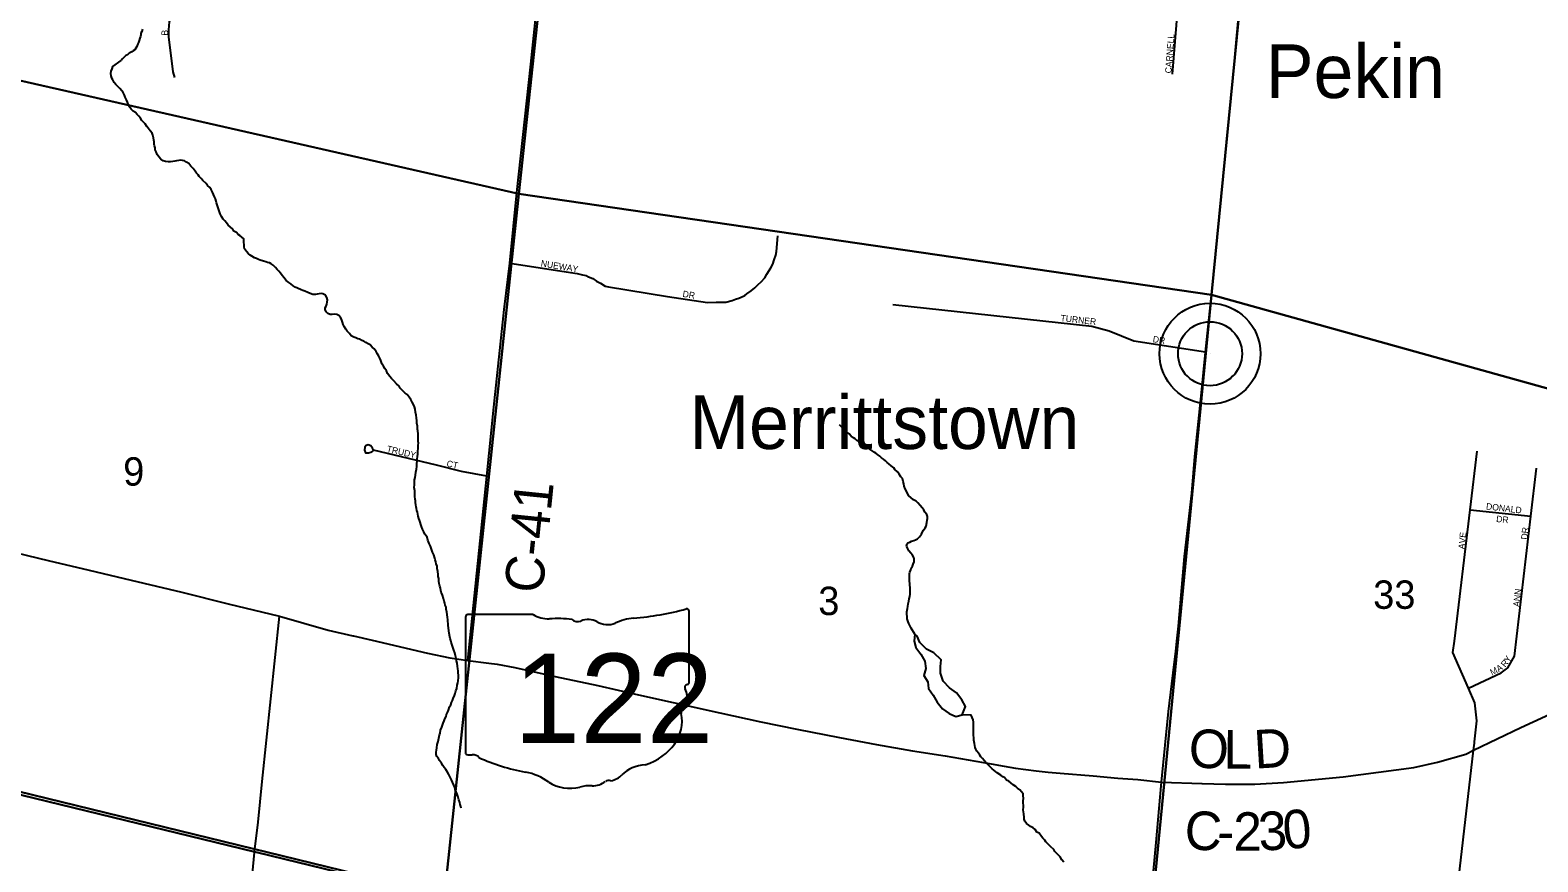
# Model space of a CAD drawing. Extents: x 0 to 1064, y 0 to 440.
# Drawn here: x 222.52 to 258.1, y 292.66 to 312.28 of the extents above; entities that cross this region are included whole.
import ezdxf

# ---------------------------------------------------------------- set-up
doc = ezdxf.new("R2010")
doc.units = 0
for name, color, linetype in [('GM_X_County_Road', 7, 'Continuous'), ('GM_X_County_Road_Text', 7, 'Continuous'), ('GM_X_Minor_Lake', 7, 'Continuous'), ('GM_X_Minor_River', 7, 'Continuous'), ('GM_X_Section', 7, 'Continuous'), ('GM_X_Section_Text', 7, 'Continuous'), ('GM_X_State_Location', 7, 'Continuous'), ('GM_X_State_Route', 7, 'Continuous'), ('GM_X_State_Shield', 7, 'Continuous'), ('GM_X_Township', 7, 'Continuous'), ('GM_X_Township_Subdivision', 7, 'Continuous'), ('GM_X_Township_Subdivision_Text', 7, 'Continuous'), ('GM_X_Unincorporated', 7, 'Continuous'), ('GM_X_Unincorporated_Location', 7, 'Continuous'), ('GM_X_Unincorporated_Text', 7, 'Continuous')]:
    doc.layers.add(name, color=color, linetype=linetype)

msp = doc.modelspace()

# ---------------------------------------------------------------- linework, layer by layer
at = {"layer": 'GM_X_County_Road'}
for points in [[(232.845, 297.415), (233.296, 301.759), (233.463, 303.386), (233.702, 305.691), (233.837, 306.783), (234.001, 308.45), (234.335, 311.479), (234.642, 314.418), (234.9, 316.803)], [(250.165, 294.513), (250.171, 294.513), (250.722, 294.492), (251.418, 294.496), (252.094, 294.534), (253.503, 294.667), (255.166, 294.889), (255.73, 295.017), (256.392, 295.206), (256.58, 295.296), (257.697, 295.829), (258.859, 296.365), (259.226, 296.54), (259.61, 296.696), (259.922, 296.816), (260.414, 296.936), (260.779, 297.03), (261.418, 297.217), (262.042, 297.399), (262.551, 297.565), (263.103, 297.778), (266.941, 299.839), (267.217, 299.997)], [(227.812, 292.884), (227.814, 292.901), (227.897, 293.599), (227.997, 294.56), (228.401, 298.462)], [(249.215, 294.545), (250.165, 294.513)], [(227.217, 256.331), (227.021, 256.544), (226.463, 257.231), (226.198, 257.65), (225.438, 259.12), (225.221, 259.508), (225.122, 259.711), (225.097, 259.973), (225.685, 266.061), (225.937, 268.726), (226.312, 273.171), (227.313, 284.338), (227.421, 286.562), (227.469, 287.662), (227.522, 288.708), (227.683, 291.298), (227.726, 291.973), (227.812, 292.884)]]:
    msp.add_lwpolyline(points, dxfattribs=at)
at = {"layer": 'GM_X_Minor_Lake'}
for points in [[(243.392, 298.033), (243.376, 297.87), (243.421, 297.716), (243.539, 297.562), (243.632, 297.395), (243.653, 297.224), (243.606, 297.061), (243.7, 296.907), (243.72, 296.754), (243.826, 296.594), (243.919, 296.433), (244.049, 296.272), (244.205, 296.165), (244.362, 296.094), (244.515, 296.133)], [(244.515, 296.133), (244.587, 296.326), (244.505, 296.486), (244.375, 296.647), (244.214, 296.767), (244.065, 296.922), (244.003, 297.113), (244.001, 297.271), (244.017, 297.428), (243.844, 297.591), (243.67, 297.68), (243.515, 297.836), (243.452, 297.989), (243.392, 298.033)]]:
    msp.add_lwpolyline(points, dxfattribs=at)
at = {"layer": 'GM_X_Minor_River'}
for points in [[(225.168, 312.302), (225.154, 312.247), (225.135, 312.211), (225.134, 312.175), (225.121, 312.133), (225.107, 312.09), (225.094, 312.036), (225.075, 311.994), (225.061, 311.958), (225.036, 311.898), (225.016, 311.856), (224.991, 311.82), (224.954, 311.796), (224.917, 311.773), (224.855, 311.738), (224.818, 311.702), (224.781, 311.685), (224.744, 311.65), (224.7, 311.608), (224.668, 311.566)], [(226.442, 308.909), (226.413, 308.958), (226.366, 309.02), (226.313, 309.077), (226.267, 309.133), (226.213, 309.171), (226.165, 309.197), (226.117, 309.21), (226.074, 309.212), (226.032, 309.207), (225.976, 309.196), (225.934, 309.192), (225.885, 309.181), (225.83, 309.177), (225.775, 309.178), (225.714, 309.18), (225.66, 309.2), (225.606, 309.238), (225.553, 309.294), (225.519, 309.35), (225.49, 309.412), (225.474, 309.461), (225.469, 309.51), (225.458, 309.552), (225.448, 309.595), (225.443, 309.644), (225.438, 309.687), (225.434, 309.741), (225.418, 309.802), (225.401, 309.852), (225.354, 309.908), (225.302, 309.97), (225.273, 310.013), (225.232, 310.069), (225.197, 310.113), (225.155, 310.151), (225.121, 310.206), (225.086, 310.25), (225.044, 310.294), (225.003, 310.337), (224.95, 310.375), (224.903, 310.419), (224.862, 310.475), (224.839, 310.518), (224.816, 310.58), (224.794, 310.641), (224.766, 310.703), (224.749, 310.752), (224.714, 310.808), (224.685, 310.851), (224.639, 310.907), (224.597, 310.945), (224.544, 311.001), (224.503, 311.051), (224.469, 311.107), (224.446, 311.15), (224.429, 311.205), (224.425, 311.26), (224.433, 311.314), (224.453, 311.368), (224.473, 311.422), (224.668, 311.566)], [(230.204, 305.023), (230.156, 305.043), (230.096, 305.075), (230.055, 305.125), (230.002, 305.181), (229.968, 305.231), (229.927, 305.293), (229.904, 305.342), (229.888, 305.391), (229.877, 305.44), (229.848, 305.495), (229.802, 305.551), (229.754, 305.577), (229.699, 305.579), (229.644, 305.574), (229.601, 305.576), (229.547, 305.596), (229.506, 305.639), (229.483, 305.689), (229.485, 305.731), (229.504, 305.773), (229.524, 305.815), (229.532, 305.869), (229.534, 305.918), (229.523, 305.973), (229.488, 306.028), (229.429, 306.061), (229.386, 306.068), (229.343, 306.063), (229.294, 306.053), (229.252, 306.048), (229.191, 306.05), (229.131, 306.07), (229.07, 306.09), (228.998, 306.123), (228.956, 306.142), (228.914, 306.155), (228.83, 306.194), (228.77, 306.221), (228.723, 306.252), (228.669, 306.297), (228.628, 306.328), (228.562, 306.379), (228.51, 306.447), (228.469, 306.491), (228.428, 306.547), (228.387, 306.597), (228.346, 306.64), (228.311, 306.684), (228.258, 306.74), (228.21, 306.766), (228.168, 306.792), (228.12, 306.805), (228.078, 306.819), (228.023, 306.833), (227.951, 306.859), (227.909, 306.872), (227.861, 306.892), (227.813, 306.912), (227.753, 306.95), (227.711, 306.976), (227.67, 307.007), (227.623, 307.057), (227.576, 307.126), (227.572, 307.168), (227.568, 307.229), (227.563, 307.272), (227.564, 307.32), (227.56, 307.363), (227.518, 307.401), (227.471, 307.438), (227.429, 307.458), (227.388, 307.508), (227.328, 307.54), (227.299, 307.589), (227.24, 307.64), (227.193, 307.684), (227.152, 307.74), (227.111, 307.783), (227.076, 307.827), (227.035, 307.889), (227.001, 307.951), (226.979, 308.018), (226.968, 308.067), (226.951, 308.116), (226.935, 308.165), (226.918, 308.208), (226.907, 308.251), (226.891, 308.3), (226.868, 308.349), (226.845, 308.405), (226.823, 308.46), (226.794, 308.522), (226.759, 308.571), (226.706, 308.621), (226.677, 308.665), (226.594, 308.734), (226.559, 308.784), (226.512, 308.828), (226.483, 308.871), (226.442, 308.909)], [(232.121, 299.64), (232.104, 299.689), (232.094, 299.738), (232.077, 299.787), (232.066, 299.83), (232.044, 299.903), (232.016, 299.971), (231.988, 300.039), (231.966, 300.112), (231.938, 300.174), (231.904, 300.254), (231.888, 300.321), (231.835, 300.389), (231.807, 300.451), (231.778, 300.512), (231.756, 300.574), (231.739, 300.617), (231.723, 300.678), (231.706, 300.721), (231.695, 300.764), (231.679, 300.819), (231.668, 300.862), (231.658, 300.911), (231.647, 300.954), (231.636, 300.996), (231.631, 301.039), (231.621, 301.088), (231.616, 301.137), (231.612, 301.179), (231.607, 301.222), (231.597, 301.283), (231.599, 301.35), (231.595, 301.417), (231.585, 301.49), (231.588, 301.556), (231.59, 301.629), (231.591, 301.672), (231.606, 301.732), (231.613, 301.786), (231.622, 301.853), (231.636, 301.925), (231.645, 301.992), (231.647, 302.052), (231.649, 302.119), (231.65, 302.162), (231.658, 302.222), (231.666, 302.282), (231.669, 302.349), (231.677, 302.416), (231.679, 302.495), (231.681, 302.537), (231.676, 302.58), (231.678, 302.622), (231.679, 302.665), (231.674, 302.707), (231.676, 302.756), (231.666, 302.829), (231.661, 302.872), (231.658, 302.938), (231.648, 303.012), (231.643, 303.066), (231.634, 303.139), (231.63, 303.2), (231.614, 303.268), (231.604, 303.341), (231.587, 303.396), (231.565, 303.451), (231.536, 303.507), (231.502, 303.568), (231.467, 303.624), (231.42, 303.686), (231.373, 303.718), (231.331, 303.756), (231.29, 303.794), (231.249, 303.837), (231.226, 303.881), (231.167, 303.937), (231.102, 304.006), (231.049, 304.068), (231.008, 304.112), (230.956, 304.186), (230.927, 304.242), (230.893, 304.304), (230.858, 304.353), (230.829, 304.403), (230.812, 304.446), (230.795, 304.489), (230.773, 304.544), (230.744, 304.594), (230.71, 304.655), (230.681, 304.699), (230.634, 304.761), (230.593, 304.805), (230.54, 304.861), (230.498, 304.88), (230.444, 304.912), (230.39, 304.944), (230.348, 304.964), (230.294, 304.99), (230.252, 305.003), (230.204, 305.023)], [(241.791, 302.802), (241.749, 302.833), (241.708, 302.877), (241.661, 302.921), (241.62, 302.971)], [(243.392, 298.033), (243.307, 298.178), (243.284, 298.221), (243.255, 298.283), (243.238, 298.326), (243.216, 298.399), (243.212, 298.454), (243.208, 298.509), (243.21, 298.557), (243.217, 298.599), (243.224, 298.642), (243.232, 298.684), (243.24, 298.75), (243.254, 298.811), (243.262, 298.865), (243.276, 298.919), (243.284, 298.974), (243.286, 299.022), (243.288, 299.083), (243.283, 299.132), (243.279, 299.186), (243.274, 299.229), (243.27, 299.284), (243.266, 299.339), (243.267, 299.387), (243.27, 299.454), (243.277, 299.496), (243.297, 299.55), (243.311, 299.592), (243.336, 299.634), (243.356, 299.688), (243.377, 299.742), (243.379, 299.802), (243.374, 299.845), (243.339, 299.895), (243.304, 299.944), (243.257, 300), (243.228, 300.044), (243.206, 300.099), (243.201, 300.142), (243.227, 300.19), (243.276, 300.206), (243.32, 300.229), (243.369, 300.24), (243.412, 300.257), (243.455, 300.28), (243.505, 300.327), (243.55, 300.392), (243.57, 300.434), (243.596, 300.488), (243.64, 300.541), (243.66, 300.583), (243.675, 300.668), (243.689, 300.722), (243.69, 300.764), (243.692, 300.813), (243.675, 300.856), (243.628, 300.912), (243.606, 300.967), (243.565, 301.017), (243.524, 301.067), (243.465, 301.129), (243.424, 301.173), (243.364, 301.205), (243.299, 301.256), (243.257, 301.294), (243.223, 301.349), (243.2, 301.405), (243.165, 301.46), (243.143, 301.528), (243.133, 301.583), (243.123, 301.638), (243.1, 301.705), (243.065, 301.749), (243.025, 301.811), (242.984, 301.86), (242.925, 301.917), (242.896, 301.96), (242.836, 302.005), (242.783, 302.049), (242.742, 302.087), (242.7, 302.124), (242.653, 302.162), (242.611, 302.194), (242.57, 302.231), (242.516, 302.27), (242.475, 302.301), (242.433, 302.327), (242.391, 302.358), (242.332, 302.397), (242.284, 302.422), (242.23, 302.454), (242.171, 302.505), (242.123, 302.531), (242.082, 302.568), (242.028, 302.6), (241.986, 302.638), (241.945, 302.664), (241.891, 302.708), (241.844, 302.758), (241.791, 302.802)], [(232.687, 293.928), (232.683, 293.971), (232.666, 294.014), (232.661, 294.062), (232.639, 294.124), (232.617, 294.191), (232.595, 294.259), (232.572, 294.314), (232.55, 294.369), (232.539, 294.418), (232.517, 294.474), (232.488, 294.541), (232.466, 294.597), (232.431, 294.658), (232.403, 294.72), (232.368, 294.782), (232.328, 294.838), (232.287, 294.888), (232.258, 294.937), (232.223, 294.993), (232.177, 295.055), (232.154, 295.098), (232.119, 295.148), (232.102, 295.191), (232.104, 295.251), (232.111, 295.294), (232.119, 295.354), (232.128, 295.427), (232.149, 295.505), (232.164, 295.583), (232.178, 295.656), (232.192, 295.698), (232.206, 295.77), (232.233, 295.842), (232.247, 295.89), (232.267, 295.938), (232.287, 295.992), (232.307, 296.04), (232.333, 296.094), (232.346, 296.136), (232.379, 296.202), (232.392, 296.244), (232.419, 296.316), (232.445, 296.37), (232.465, 296.418), (232.485, 296.472), (232.505, 296.514), (232.532, 296.586), (232.545, 296.634), (232.566, 296.694), (232.586, 296.754), (232.6, 296.827), (232.608, 296.887), (232.616, 296.935), (232.625, 297.008), (232.626, 297.056), (232.616, 297.13), (232.618, 297.172), (232.613, 297.215), (232.603, 297.282), (232.593, 297.349), (232.583, 297.404), (232.573, 297.459), (232.557, 297.526), (232.54, 297.593), (232.518, 297.655), (232.501, 297.704), (232.479, 297.771), (232.451, 297.845), (232.447, 297.888), (232.43, 297.931), (232.425, 297.973), (232.404, 298.059), (232.399, 298.114), (232.389, 298.181), (232.385, 298.235), (232.381, 298.284), (232.376, 298.333), (232.372, 298.382), (232.367, 298.424), (232.363, 298.497), (232.353, 298.552), (232.337, 298.625), (232.333, 298.674), (232.316, 298.717), (232.305, 298.766), (232.288, 298.809), (232.272, 298.876), (232.25, 298.95), (232.222, 299.024), (232.212, 299.066), (232.201, 299.115), (232.19, 299.164), (232.174, 299.225), (232.164, 299.286), (232.16, 299.347), (232.149, 299.396), (232.145, 299.445), (232.141, 299.512), (232.125, 299.585), (232.121, 299.64)], [(245.957, 294.168), (245.953, 294.223), (245.948, 294.266), (245.913, 294.315), (245.872, 294.365), (245.818, 294.403), (245.777, 294.441), (245.717, 294.479), (245.658, 294.523), (245.611, 294.567), (245.557, 294.593), (245.51, 294.649), (245.468, 294.669), (245.421, 294.707), (245.337, 294.764), (245.295, 294.79), (245.219, 294.859), (245.171, 294.903), (245.124, 294.953), (245.071, 295.003), (245.03, 295.053), (244.989, 295.097), (244.954, 295.14), (244.931, 295.183), (244.896, 295.227), (244.855, 295.277), (244.832, 295.32), (244.815, 295.363), (244.81, 295.406), (244.8, 295.454), (244.79, 295.534), (244.786, 295.595), (244.782, 295.643), (244.777, 295.698), (244.779, 295.753), (244.781, 295.795), (244.783, 295.856), (244.778, 295.904), (244.78, 295.959), (244.77, 296.014), (244.747, 296.069), (244.725, 296.125), (244.515, 296.133)], [(246.912, 292.657), (246.865, 292.714), (246.824, 292.782), (246.754, 292.851), (246.701, 292.907), (246.672, 292.95), (246.607, 293.013), (246.548, 293.069), (246.489, 293.132), (246.46, 293.175), (246.419, 293.219), (246.384, 293.263), (246.325, 293.337), (246.277, 293.363), (246.237, 293.425), (246.189, 293.463), (246.123, 293.495), (246.082, 293.527), (246.028, 293.571), (245.987, 293.621), (245.977, 293.67), (245.972, 293.712), (245.963, 293.798), (245.958, 293.84), (245.954, 293.889), (245.956, 293.95), (245.957, 293.998), (245.953, 294.047), (245.954, 294.095), (245.957, 294.168)]]:
    msp.add_lwpolyline(points, dxfattribs=at)
at = {"layer": 'GM_X_Section'}
for points in [[(219.098, 327.846), (235.843, 325.091), (234.053, 308.422), (219.433, 311.739), (217.525, 311.775)], [(235.843, 325.091), (252.001, 322.359), (250.392, 306.037), (234.053, 308.422)], [(252.001, 322.359), (268.72, 318.199), (267.132, 301.372), (250.392, 306.037)], [(234.053, 308.422), (232.294, 291.87), (215.966, 295.854), (217.525, 311.775), (219.433, 311.739)], [(234.053, 308.422), (250.392, 306.037), (248.821, 289.79), (232.294, 291.87)], [(250.392, 306.037), (267.132, 301.372), (265.757, 288.473), (248.821, 289.79)], [(232.294, 291.87), (230.695, 275.436), (214.149, 277.17), (215.966, 295.854)]]:
    msp.add_lwpolyline(points, close=True, dxfattribs=at)
at = {"layer": 'GM_X_State_Route'}
for points in [[(249.578, 297.871), (249.615, 298.226), (249.761, 299.867), (249.927, 301.362), (250, 302.225), (250.16, 303.729), (250.252, 304.689), (250.434, 306.4), (250.596, 308.064), (250.767, 309.807), (250.893, 311.042), (250.976, 311.98), (251.079, 313.096)], [(221.936, 300.016), (222.945, 299.775), (223.915, 299.543), (224.903, 299.308), (226.1, 299.024), (227.191, 298.75), (228.401, 298.462), (229.555, 298.131), (230.134, 297.998)], [(230.134, 297.998), (230.151, 297.995), (230.59, 297.894), (231.898, 297.584), (232.424, 297.478), (232.845, 297.415), (233.343, 297.351), (233.536, 297.322), (233.957, 297.244), (234.911, 297.037), (235.915, 296.819), (236.874, 296.606), (237.69, 296.424), (238.792, 296.178), (239.761, 295.966), (240.611, 295.795), (241.62, 295.599), (242.488, 295.43), (243.342, 295.279), (244.109, 295.161), (245.013, 295.006), (245.241, 294.966)], [(249.215, 294.545), (249.378, 296.206), (249.517, 297.32), (249.551, 297.624), (249.578, 297.871)], [(245.241, 294.966), (245.367, 294.944), (245.77, 294.869), (246.259, 294.806), (246.54, 294.778), (246.824, 294.756), (246.825, 294.756)], [(246.825, 294.756), (247.599, 294.693), (248.188, 294.637), (248.654, 294.607), (249.215, 294.545)], [(248.911, 291.159), (248.941, 291.517), (249.087, 293.119), (249.215, 294.545)]]:
    msp.add_lwpolyline(points, dxfattribs=at)
at = {"layer": 'GM_X_State_Shield'}
for p, q in [((234.392, 298.497), (232.847, 298.497)), ((238.069, 296.901), (238.069, 298.576)), ((232.795, 298.442), (232.795, 295.24)), ((238.068, 296.902), (238.069, 296.901))]:
    msp.add_line(p, q, dxfattribs=at)
for centre, major_axis, start_param, end_param in [((232.856, 298.449), (0.0611, 0), 1.712693, 3.28349), ((234.759, 298.869), (0.593, 0), 4.042523, 4.731795), ((236.19, 302.862), (5.592, 0), 4.814394, 5.042369), ((238.01, 298.583), (0.0587, 0), 6.141152, 7.989035), ((234.956, 296.699), (2.127, 0), 1.404758, 1.657858), ((235.439, 298.465), (0.171, 0), 3.836095, 5.185415), ((235.69, 298.095), (0.355, 0), 0.950623, 2.079405), ((236.148, 298.603), (0.428, 0), 4.081561, 5.145723), ((236.903, 297.519), (1.125, 0), 1.699011, 2.107814), ((238.055, 296.778), (0.0909, 0), 1.883978, 3.671073), ((237.477, 296.567), (0.545, 0), 5.934695, 6.695948), ((238.006, 296.895), (0.0628, 0), 5.05454, 6.418171), ((238.279, 296.2), (0.397, 0), 2.387724, 3.262537), ((236.503, 295.987), (1.399, 0), 5.101752, 6.440018), ((232.856, 295.233), (0.0616, 0), 3.00124, 4.508301), ((232.866, 295.56), (0.47, 0), 4.665946, 4.897461), ((232.962, 295.055), (0.17, 0), 0.519207, 1.627899), ((235.103, 297.932), (4.038, 0), 4.195997, 4.488961), ((237.093, 294.341), (0.766, 0), 1.647645, 2.488434), ((233.899, 293.801), (1.264, 0), 0.823519, 1.323587), ((235.787, 294.799), (0.427, 0), 4.691044, 5.507374), ((236.174, 294.489), (0.12, 0), 1.147584, 2.315152), ((236.123, 294.929), (0.452, 0), 4.937069, 5.64225), ((235.266, 295.039), (0.802, 0), 4.026481, 4.996735), ((235.729, 293.932), (0.659, 0), 1.495662, 1.94098)]:
    msp.add_ellipse(centre, major_axis=major_axis, ratio=0.8, start_param=start_param, end_param=end_param, dxfattribs=at)
at = {"layer": 'GM_X_Township'}
for points in [[(132.309, 292.479), (132.404, 293.708), (132.476, 294.635), (132.789, 298.696), (132.878, 300.691), (132.881, 300.737), (132.884, 300.775), (143.744, 299.709), (149.277, 299.165), (172.793, 296.856), (182.432, 295.909), (187.261, 295.09), (198.877, 293.237), (202.449, 293.668), (202.589, 293.69), (207.617, 294.604), (215.892, 295.803), (227.814, 292.902), (227.881, 292.885), (232.24, 291.824)], [(232.24, 291.824), (227.881, 292.885), (227.814, 292.902), (215.892, 295.803)]]:
    msp.add_lwpolyline(points, dxfattribs=at)
at = {"layer": 'GM_X_Township_Subdivision'}
for points in [[(225.934, 311.168), (225.898, 311.3), (225.79, 312.128), (225.796, 312.29), (225.81, 312.482), (225.882, 312.747), (225.976, 312.95), (226.09, 313.076), (226.27, 313.208), (226.486, 313.352), (226.594, 313.43), (226.726, 313.556), (226.804, 313.676), (226.858, 313.784), (226.906, 314.06), (227.36, 318.145)], [(249.724, 314.428), (249.464, 311.246)], [(233.837, 306.783), (235.429, 306.539), (235.556, 306.512), (235.636, 306.492), (235.696, 306.466), (235.796, 306.426), (235.882, 306.359), (235.982, 306.312), (236.089, 306.246), (236.169, 306.226), (237.561, 305.999), (238.501, 305.859), (238.707, 305.866), (238.934, 305.866), (239.087, 305.906), (239.167, 305.933), (239.24, 305.959), (239.3, 305.986), (239.38, 306.019), (239.427, 306.066), (239.533, 306.133), (239.62, 306.206), (239.7, 306.279), (239.773, 306.346), (239.859, 306.439), (239.906, 306.526), (239.999, 306.672), (240.046, 306.765), (240.073, 306.865), (240.119, 306.972), (240.133, 307.059), (240.165, 307.43)], [(250.252, 304.689), (248.563, 304.945), (247.983, 305.18), (247.57, 305.29), (242.872, 305.801)], [(233.296, 301.759), (232.702, 301.874), (232.109, 302.02), (230.786, 302.332), (230.622, 302.376), (230.6, 302.422), (230.557, 302.478), (230.5, 302.501), (230.449, 302.485), (230.419, 302.446), (230.413, 302.377), (230.435, 302.314), (230.505, 302.309), (230.561, 302.329), (230.611, 302.359)], [(256.603, 295.497), (256.658, 295.99), (256.611, 296.41), (256.457, 296.763), (256.09, 297.605), (256.125, 297.866), (256.499, 300.967), (256.666, 302.351)], [(256.457, 296.763), (257.226, 297.118), (257.387, 297.243), (257.546, 297.513), (257.933, 300.816), (258.065, 301.951)], [(256.499, 300.967), (257.933, 300.816)], [(256.09, 291.07), (256.58, 295.296), (256.599, 295.465), (256.603, 295.497)]]:
    msp.add_lwpolyline(points, dxfattribs=at)
at = {"layer": 'GM_X_Unincorporated'}
for radius in [1.19, 0.755]:
    msp.add_circle((250.36, 304.65), radius, dxfattribs=at)
at = {"layer": 'GM_X_Unincorporated_Location'}
msp.add_line((250.36, 304.65), (250.36, 304.65), dxfattribs=at)

# ---------------------------------------------------------------- texts
at = {"layer": 'GM_X_County_Road_Text'}
for s, height, rotation, p in [('C-41', 0.9091, 84.1533, (234.608, 298.975)), ('O', 0.909, 357.8283, (249.845, 294.892)), ('L', 0.909, 359.7279, (250.677, 294.861)), ('D', 0.909, 3.4515, (251.421, 294.86)), ('C', 0.909, 357.3138, (249.744, 292.962)), ('2', 0.909, 359.9855, (250.909, 292.923)), ('3', 0.909, 3.0812, (251.523, 292.924)), ('0', 0.909, 4.9893, (252.115, 292.956)), ('-', 0.909, 359.4392, (250.526, 292.926))]:
    msp.add_text(s, height=height, rotation=rotation, dxfattribs=at).set_placement(p)
at = {"layer": 'GM_X_Section_Text'}
for s, height, p in [('9', 0.67, (224.716, 301.537)), ('33', 0.6697, (254.21, 298.631)), ('3', 0.67, (241.116, 298.484))]:
    msp.add_text(s, height=height, rotation=0, dxfattribs=at).set_placement(p)
at = {"layer": 'GM_X_State_Location'}
msp.add_text('122', height=0.00303, rotation=0, dxfattribs=at).set_placement((234.303, 296.407))
for s in ['s', 'r']:
    msp.add_text(s, height=0.00303, dxfattribs=at).set_placement((235.373, 296.628))
at = {"layer": 'GM_X_State_Shield'}
msp.add_text('122', height=2.1094, dxfattribs=at).set_placement((233.933, 295.466))
at = {"layer": 'GM_X_Township_Subdivision_Text'}
for s, height, rotation, p in [('B', 0.152, 87.5463, (225.768, 312.151)), ('CARNELL', 0.1515, 85.5352, (249.448, 311.258)), ('NUEWAY', 0.1515, 350.6917, (234.561, 306.711)), ('DR', 0.1515, 351.0309, (237.907, 305.991)), ('TURNER', 0.1515, 353.7737, (246.826, 305.418)), ('DR', 0.1515, 351.0327, (249.001, 304.924)), ('TRUDY', 0.1515, 346.8259, (230.923, 302.337)), ('CT', 0.1515, 347.4789, (232.336, 301.991)), ('DONALD', 0.1515, 353.2341, (256.866, 300.978)), ('DR', 0.1515, 353.9946, (257.106, 300.681)), ('AVE', 0.1515, 84.0902, (256.368, 300.032)), ('DR', 0.1515, 83.9832, (257.848, 300.259)), ('ANN', 0.1515, 84.1413, (257.662, 298.672)), ('R', 0.152, 50.5498, (257.324, 297.24)), ('Y', 0.152, 59.497, (257.415, 297.353)), ('M', 0.152, 25.8564, (257.012, 297.055)), ('A', 0.152, 32.0813, (257.171, 297.134))]:
    msp.add_text(s, height=height, rotation=rotation, dxfattribs=at).set_placement(p)
at = {"layer": 'GM_X_Unincorporated_Text'}
for s, height, p in [('Pekin', 1.2636, (251.676, 310.682)), ('Merrittstown', 1.26364, (238.076, 302.402))]:
    msp.add_text(s, height=height, rotation=0, dxfattribs=at).set_placement(p)

doc.saveas('drawing.dxf')
